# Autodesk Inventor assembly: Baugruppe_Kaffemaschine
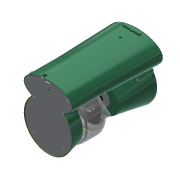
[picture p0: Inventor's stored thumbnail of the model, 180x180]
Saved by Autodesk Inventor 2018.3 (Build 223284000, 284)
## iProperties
Created: 2019-01
Part Number: Baugruppe_Kaffemaschine
Material: Generisch
Document SubType Name: Assembly
Designer: zand
Title: KAFFEEMASCHINE1_ZAND_ASM
Sending System: CREO PARAMETRIC BY PTC INC, 2018100
Preprocessor: CREO PARAMETRIC BY PTC INC, 2018100
Author: zand
Revision Number: 44LAST_VERSION
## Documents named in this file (17)
- D:\10_CAD-ÜBUNGEN\KAFFEEMASCHINE\Workspaces\Arbeitsbereich\Baugruppe_Kaffemaschine.iam
- Y:\KAFFEEMASCHINE\Creo5-STEP-Inventor\STEP\WASSERTANK_ZAND_AF0.ipt
- Y:\KAFFEEMASCHINE\Creo5-STEP-Inventor\STEP\WASSERTANKDECKEL_ZAND.ipt
- Y:\KAFFEEMASCHINE\Creo5-STEP-Inventor\STEP\WASSERAUSLASSDECKEL_ZAND.ipt
- Y:\KAFFEEMASCHINE\Creo5-STEP-Inventor\STEP\ABSTELLFLCHE_ZAND0.ipt
- Y:\KAFFEEMASCHINE\Creo5-STEP-Inventor\STEP\GEHAEUSE-FILTERKAMMER_ZAND.ipt
- Y:\KAFFEEMASCHINE\Creo5-STEP-Inventor\STEP\BAUGRUPPE_GLASSKANNE_ERFANIAN_ASM.iam
- Y:\KAFFEEMASCHINE\Creo5-STEP-Inventor\STEP\FILTERKAMMER_ZAND.ipt
- Y:\KAFFEEMASCHINE\Creo5-STEP-Inventor\STEP\DURCHLASS_ERFANIAN.ipt
- Y:\KAFFEEMASCHINE\Creo5-STEP-Inventor\STEP\UNTERPLATTE_ZAND.ipt
- Y:\KAFFEEMASCHINE\Creo5-STEP-Inventor\STEP\WASSERDURCHLASS_ERFANIAN_ASM.iam
- Y:\KAFFEEMASCHINE\Creo5-STEP-Inventor\STEP\SHALTER_ERFANIAN_ASM.iam
- Y:\KAFFEEMASCHINE\Creo5-STEP-Inventor\STEP\DICHTUNG-DURCHLASS_ZAND.ipt
- Y:\KAFFEEMASCHINE\Creo5-STEP-Inventor\STEP\BLACKBOX_ZAND.ipt
- Y:\KAFFEEMASCHINE\Creo5-STEP-Inventor\STEP\SCHLAUCH_ZAND.ipt
- Y:\KAFFEEMASCHINE\Creo5-STEP-Inventor\STEP\Spiralfeder Auslass.ipt
- Y:\KAFFEEMASCHINE\Creo5-STEP-Inventor\STEP\Sprengring Kanne.ipt
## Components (16 placed, 16 different names)
1. Wasstank
2. Wassertankdeckel
3. Wasserauslassdeckel
4. Abstellflaeche
5. Filterkammergehaeuse
6. Baugruppe_Glaskanne [sub-assembly] — Passend:8, Passend:9
7. Fiterkammer
8. Durchlass — Passend:5
9. Unterplatte
10. Baugruppe_Wasserdurchlass [sub-assembly]
11. Baugruppe_Schalter [sub-assembly]
12. Dichtung-Durchlass
13. Blackbox
14. Schlauch
15. Spiralfeder Auslass:1 — Passend:5
16. Sprengring Kanne:1 — Passend:8, Passend:9
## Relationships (3: Mate 3)
- Passend:5 [Mate]: Durchlass ↔ Spiralfeder Auslass:1
- Passend:8 [Mate]: Baugruppe_Glaskanne ↔ Sprengring Kanne:1
- Passend:9 [Mate]: Baugruppe_Glaskanne ↔ Sprengring Kanne:1
